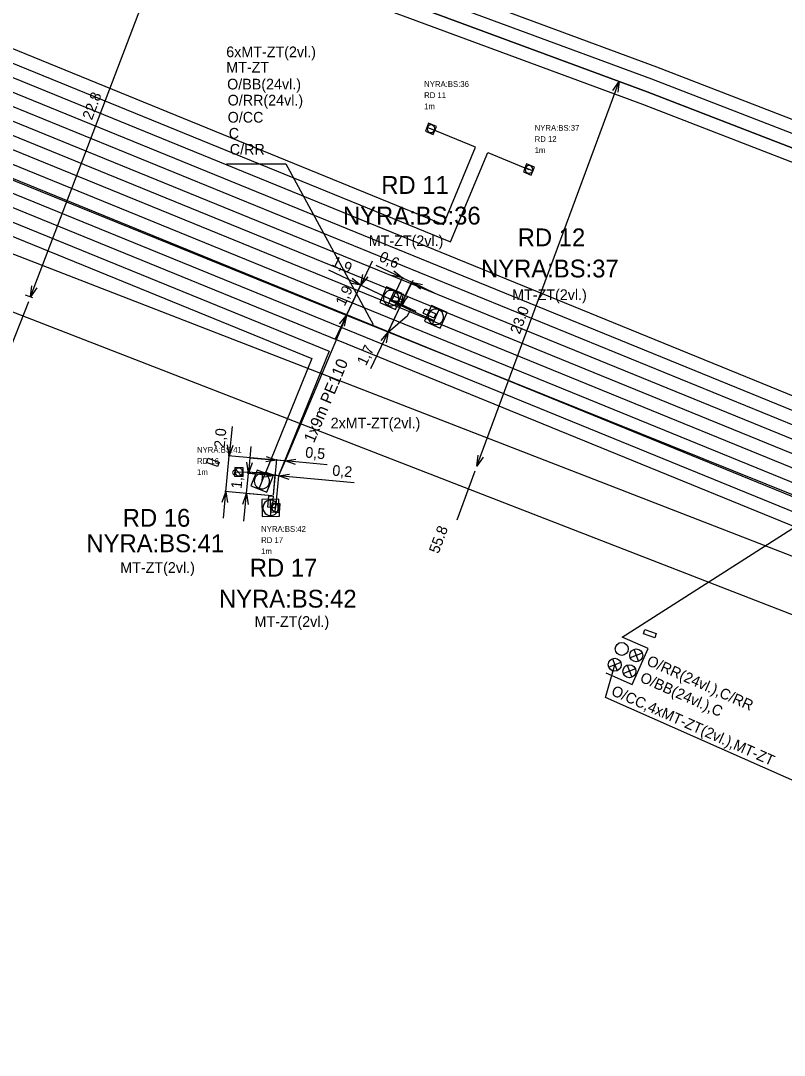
# Model space of a CAD drawing. Extents: x -836739 to -834468, y -1071001 to -1070126.
# Drawn here: x -836340.8 to -836298, y -1070459.3 to -1070401.3 of the extents above; entities that cross this region are included whole.
import ezdxf

# ---------------------------------------------------------------- set-up
doc = ezdxf.new("R2010")
doc.units = 0
for name, color, linetype in [('f001_pol_linie', 7, 'Continuous'), ('f002_inz_linie_mimo_CETIN', 7, 'Continuous'), ('f003_opt_sit_texty', 7, 'Continuous'), ('f003_opt_sit_znacky', 7, 'Continuous'), ('f003_vynaseci_cary', 7, 'Continuous'), ('f006_osa_trasy', 7, 'Continuous'), ('f006_stp_koty', 7, 'Continuous'), ('f006_stp_linie', 7, 'Continuous'), ('f006_stp_texty', 7, 'Continuous'), ('f007_rezkynet_linie', 7, 'Continuous'), ('f007_rezkynet_texty', 7, 'Continuous'), ('f007_rezkynet_znacky', 7, 'Continuous'), ('f309_rozvadec_opt', 7, 'Continuous'), ('f309_rozvadec_opt_ann', 7, 'Continuous'), ('f309_trubicka', 7, 'Continuous'), ('f309_trubka', 7, 'Continuous')]:
    doc.layers.add(name, color=color, linetype=linetype)

msp = doc.modelspace()

# ---------------------------------------------------------------- linework, layer by layer
at = {"layer": 'f001_pol_linie'}
for points in [[(-836015.21, -1070459.49), (-836021.84, -1070470.53), (-836029.29, -1070480.55), (-836039.31, -1070497.89), (-836043.1, -1070509.87), (-836044.22, -1070522.08), (-836111.13, -1070487.77), (-836123.74, -1070483.53), (-836128.61, -1070481.99), (-836211.76, -1070460.38), (-836245.95, -1070449.75), (-836279.43, -1070438.33), (-836363.94, -1070405.58)], [(-836046.6, -1070544.35), (-836045.64, -1070538.23), (-836044.38, -1070528.39), (-836045.14, -1070525.37), (-836047.92, -1070523.71), (-836112.97, -1070490.6), (-836124.66, -1070486.54), (-836132.47, -1070484.33), (-836212.77, -1070463.28), (-836247.95, -1070452.55), (-836280.73, -1070441.12), (-836361.89, -1070409.63)]]:
    msp.add_lwpolyline(points, dxfattribs=at)
at = {"layer": 'f002_inz_linie_mimo_CETIN'}
for points in [[(-836319.98, -1070416.95), (-836319.87, -1070416.72), (-836319.28, -1070417), (-836319.39, -1070417.23)], [(-836319.98, -1070416.95), (-836319.87, -1070416.72), (-836319.28, -1070417), (-836319.39, -1070417.23)], [(-836319.98, -1070416.95), (-836319.39, -1070417.23)], [(-836319.98, -1070416.95), (-836319.39, -1070417.23)], [(-836318.22, -1070417.68), (-836318.12, -1070417.45), (-836317.52, -1070417.72), (-836317.62, -1070417.95)], [(-836318.22, -1070417.68), (-836318.12, -1070417.45), (-836317.52, -1070417.72), (-836317.62, -1070417.95)], [(-836318.22, -1070417.68), (-836317.62, -1070417.95)], [(-836318.22, -1070417.68), (-836317.62, -1070417.95)], [(-836329.68, -1070426.06), (-836329.77, -1070426.29), (-836330.38, -1070426.06), (-836330.29, -1070425.83)], [(-836329.68, -1070426.06), (-836329.77, -1070426.29), (-836330.38, -1070426.06), (-836330.29, -1070425.83)], [(-836330.29, -1070425.83), (-836329.68, -1070426.06)], [(-836330.29, -1070425.83), (-836329.68, -1070426.06)], [(-836326.7, -1070428.6), (-836326.95, -1070428.58), (-836326.89, -1070427.93), (-836326.64, -1070427.95)], [(-836326.7, -1070428.6), (-836326.95, -1070428.58), (-836326.89, -1070427.93), (-836326.64, -1070427.95)], [(-836326.64, -1070427.95), (-836326.7, -1070428.6)], [(-836326.64, -1070427.95), (-836326.7, -1070428.6)], [(-836305.14, -1070435.66), (-836305.22, -1070435.9), (-836305.86, -1070435.68), (-836305.78, -1070435.44)], [(-836305.14, -1070435.66), (-836305.22, -1070435.9), (-836305.86, -1070435.68), (-836305.78, -1070435.44)], [(-836305.78, -1070435.44), (-836305.14, -1070435.66)], [(-836305.78, -1070435.44), (-836305.14, -1070435.66)]]:
    msp.add_lwpolyline(points, dxfattribs=at)
at = {"layer": 'f003_opt_sit_znacky'}
for p, q in [((-836319.859, -1070416.443), (-836320.201, -1070417.237)), ((-836319.859, -1070416.444), (-836319.859, -1070416.443)), ((-836317.345, -1070417.495), (-836317.695, -1070418.285)), ((-836317.345, -1070417.496), (-836317.345, -1070417.495)), ((-836327.121, -1070426.708), (-836327.439, -1070427.512)), ((-836327.122, -1070426.709), (-836327.121, -1070426.708)), ((-836326.777, -1070429.042), (-836326.803, -1070428.178)), ((-836326.777, -1070429.041), (-836326.777, -1070429.042))]:
    msp.add_line(p, q, dxfattribs=at)
for points in [[(-836320.658, -1070417.092), (-836319.777, -1070417.472), (-836319.397, -1070416.59), (-836320.279, -1070416.21)], [(-836318.151, -1070418.135), (-836317.274, -1070418.525), (-836316.884, -1070417.647), (-836317.761, -1070417.257)], [(-836327.9, -1070427.381), (-836327.007, -1070427.734), (-836326.655, -1070426.841), (-836327.548, -1070426.488)], [(-836326.327, -1070428.116), (-836327.287, -1070428.145), (-836327.258, -1070429.104), (-836326.298, -1070429.075)]]:
    msp.add_lwpolyline(points, close=True, dxfattribs=at)
for centre, start, end in [((-836320.027, -1070416.841), 67.04609, 246.31849), ((-836320.027, -1070416.842), 246.27775, 67.08598), ((-836317.517, -1070417.891), 66.40131, 245.67371), ((-836317.517, -1070417.892), 245.63296, 66.4412), ((-836327.277, -1070427.111), 68.82282, 248.09523), ((-836327.277, -1070427.112), 248.05448, 68.86271), ((-836326.793, -1070428.61), 91.33116, 272.13939), ((-836326.793, -1070428.61), 272.0995, 91.37191)]:
    msp.add_arc(centre, 0.432, start, end, dxfattribs=at)
at = {"layer": 'f003_vynaseci_cary'}
msp.add_lwpolyline([(-836329.27, -1070409.3), (-836325.94, -1070409.3), (-836321.04, -1070418.33)], dxfattribs=at)
at = {"layer": 'f006_osa_trasy'}
for points in [[(-836259.51, -1070422.49), (-836273.33, -1070418.13), (-836279.63, -1070415.33), (-836305.65, -1070405.26), (-836332.15, -1070395.46), (-836355.51, -1070386.15), (-836363.32, -1070381.37), (-836370.68, -1070374.62), (-836386.63, -1070361.4), (-836412.6, -1070344.19), (-836444.52, -1070318.16), (-836450.35, -1070293.64), (-836451.12, -1070284.95), (-836453.47, -1070277.02), (-836456.68, -1070270.62)], [(-836322.53, -1070417.81), (-836341.09, -1070410.29), (-836350.1, -1070406.54)], [(-836318.94, -1070417.52), (-836320.09, -1070416.97), (-836320.03, -1070416.84)], [(-836322.53, -1070417.81), (-836325.98, -1070425.98), (-836326.34, -1070426.82)], [(-836320.19, -1070418.75), (-836322.53, -1070417.81)], [(-836320.19, -1070418.75), (-836319.1, -1070417.82), (-836318.94, -1070417.52)], [(-836318.94, -1070417.52), (-836317.61, -1070418.1), (-836317.52, -1070417.89)], [(-836288.87, -1070431.6), (-836297.25, -1070427.97), (-836320.19, -1070418.75)], [(-836326.34, -1070426.82), (-836327.25, -1070426.64), (-836327.28, -1070427.11)], [(-836326.34, -1070426.82), (-836326.51, -1070428.61), (-836326.79, -1070428.61)]]:
    msp.add_lwpolyline(points, dxfattribs=at)
at = {"layer": 'f006_stp_koty'}
for p, q in [((-836321.085, -1070414.765), (-836321.728, -1070416.12)), ((-836320.88, -1070414.993), (-836319.388, -1070415.702)), ((-836323.536, -1070415.262), (-836321.728, -1070416.12)), ((-836322.53, -1070417.81), (-836321.728, -1070416.12)), ((-836322.504, -1070417.756), (-836321.702, -1070416.066)), ((-836320.034, -1070416.924), (-836321.782, -1070416.095)), ((-836319.98, -1070416.95), (-836321.728, -1070416.12)), ((-836320.164, -1070418.696), (-836318.836, -1070415.897)), ((-836319.954, -1070416.896), (-836319.362, -1070415.648)), ((-836318.811, -1070415.844), (-836319.454, -1070417.2)), ((-836319.388, -1070415.702), (-836318.862, -1070415.951)), ((-836317.507, -1070416.594), (-836318.862, -1070415.951)), ((-836320.19, -1070418.75), (-836319.454, -1070417.2)), ((-836318.625, -1070417.593), (-836319.98, -1070416.95)), ((-836319.926, -1070416.976), (-836319.4, -1070417.225)), ((-836323.173, -1070419.165), (-836322.53, -1070417.81)), ((-836321.162, -1070420.798), (-836320.19, -1070418.75)), ((-836328.957, -1070424.043), (-836329.109, -1070425.691)), ((-836327.9, -1070425.17), (-836328.038, -1070426.663)), ((-836329.295, -1070427.705), (-836329.109, -1070425.691)), ((-836326.04, -1070425.974), (-836329.169, -1070425.686)), ((-836327.948, -1070425.798), (-836326.454, -1070425.936)), ((-836326.634, -1070427.89), (-836326.449, -1070425.876)), ((-836325.98, -1070425.98), (-836326.454, -1070425.936)), ((-836323.623, -1070426.198), (-836325.98, -1070425.98)), ((-836326.4, -1070426.814), (-836328.098, -1070426.658)), ((-836328.144, -1070427.811), (-836328.038, -1070426.663)), ((-836328.028, -1070426.664), (-836326.534, -1070426.802)), ((-836326.634, -1070427.89), (-836326.529, -1070426.742)), ((-836326.34, -1070426.82), (-836326.534, -1070426.802)), ((-836322.107, -1070427.211), (-836326.34, -1070426.82)), ((-836329.433, -1070429.199), (-836329.295, -1070427.705)), ((-836326.7, -1070427.944), (-836329.355, -1070427.699)), ((-836328.288, -1070429.366), (-836328.144, -1070427.811)), ((-836326.7, -1070427.944), (-836328.204, -1070427.806))]:
    msp.add_line(p, q, dxfattribs=at)
for points in [[(-836340.268, -1070416.773), (-836332.149, -1070395.46)], [(-836315.213, -1070426.276), (-836307.226, -1070404.677)], [(-836307.574, -1070405.187), (-836307.226, -1070404.677), (-836307.293, -1070405.291)], [(-836321.335, -1070415.643), (-836321.728, -1070416.12), (-836321.606, -1070415.514)], [(-836319.865, -1070415.309), (-836319.388, -1070415.702), (-836319.994, -1070415.58)], [(-836339.914, -1070416.265), (-836340.268, -1070416.773), (-836340.194, -1070416.158)], [(-836322.206, -1070415.728), (-836321.728, -1070416.12), (-836322.335, -1070415.999)], [(-836318.384, -1070416.344), (-836318.862, -1070415.951), (-836318.255, -1070416.073)], [(-836340.143, -1070416.821), (-836340.548, -1070416.666)], [(-836319.061, -1070416.722), (-836319.454, -1070417.2), (-836319.332, -1070416.593)], [(-836340.379, -1070417.053), (-836341.625, -1070420.232)], [(-836319.502, -1070417.343), (-836319.98, -1070416.95), (-836319.374, -1070417.072)], [(-836322.923, -1070418.288), (-836322.53, -1070417.81), (-836322.652, -1070418.416)], [(-836320.583, -1070419.228), (-836320.19, -1070418.75), (-836320.312, -1070419.356)], [(-836328.905, -1070425.107), (-836329.109, -1070425.691), (-836329.204, -1070425.08)], [(-836327.834, -1070426.08), (-836328.038, -1070426.663), (-836328.132, -1070426.052)], [(-836327.038, -1070425.732), (-836326.454, -1070425.936), (-836327.065, -1070426.03)], [(-836325.396, -1070426.185), (-836325.98, -1070425.98), (-836325.369, -1070425.886)], [(-836314.864, -1070425.765), (-836315.213, -1070426.276), (-836315.145, -1070425.661)], [(-836327.118, -1070426.598), (-836326.534, -1070426.802), (-836327.145, -1070426.896)], [(-836315.317, -1070426.557), (-836316.329, -1070429.293)], [(-836325.756, -1070427.025), (-836326.34, -1070426.82), (-836325.729, -1070426.726)], [(-836329.5, -1070428.289), (-836329.295, -1070427.705), (-836329.201, -1070428.316)], [(-836328.349, -1070428.395), (-836328.144, -1070427.811), (-836328.05, -1070428.422)]]:
    msp.add_lwpolyline(points, dxfattribs=at)
at = {"layer": 'f006_stp_linie'}
msp.add_lwpolyline([(-836322.53, -1070417.81), (-836325.98, -1070425.98)], dxfattribs=at)
at = {"layer": 'f007_rezkynet_linie'}
for points in [[(-836307.058, -1070435.86), (-836295.973, -1070428.796)], [(-836296.531, -1070444.332), (-836307.992, -1070439.257), (-836307.472, -1070437.416)]]:
    msp.add_lwpolyline(points, dxfattribs=at)
at = {"layer": 'f007_rezkynet_znacky'}
for p, q in [((-836305.595, -1070436.508), (-836307.058, -1070435.86)), ((-836306.488, -1070438.526), (-836305.595, -1070436.508)), ((-836307.603, -1070437.077), (-836307.341, -1070437.754)), ((-836305.927, -1070436.758), (-836306.605, -1070437.019)), ((-836306.397, -1070436.55), (-836306.135, -1070437.227)), ((-836307.133, -1070437.285), (-836307.811, -1070437.546)), ((-836306.311, -1070437.649), (-836306.988, -1070437.91)), ((-836306.781, -1070437.441), (-836306.518, -1070438.118)), ((-836307.966, -1070437.872), (-836306.503, -1070438.519))]:
    msp.add_line(p, q, dxfattribs=at)
for centre in [(-836307.08, -1070436.528), (-836306.266, -1070436.889), (-836307.472, -1070437.416), (-836306.65, -1070437.78)]:
    msp.add_circle(centre, 0.363, dxfattribs=at)
at = {"layer": 'f309_rozvadec_opt'}
for p, q in [((-836317.989, -1070407.257), (-836317.59, -1070407.422)), ((-836317.989, -1070407.257), (-836317.989, -1070407.257)), ((-836312.089, -1070409.699), (-836312.488, -1070409.534)), ((-836312.089, -1070409.699), (-836312.089, -1070409.699)), ((-836328.786, -1070426.596), (-836328.354, -1070426.607)), ((-836328.785, -1070426.596), (-836328.786, -1070426.596)), ((-836326.529, -1070428.825), (-836326.488, -1070428.395)), ((-836326.529, -1070428.825), (-836326.529, -1070428.825))]:
    msp.add_line(p, q, dxfattribs=at)
for points in [[(-836317.659, -1070407.652), (-836317.475, -1070407.208), (-836317.919, -1070407.025), (-836318.103, -1070407.468)], [(-836312.419, -1070409.304), (-836312.603, -1070409.748), (-836312.159, -1070409.931), (-836311.975, -1070409.488)], [(-836328.337, -1070426.847), (-836328.324, -1070426.367), (-836328.803, -1070426.354), (-836328.816, -1070426.834)], [(-836326.248, -1070428.394), (-836326.726, -1070428.348), (-836326.771, -1070428.826), (-836326.294, -1070428.872)]]:
    msp.add_lwpolyline(points, close=True, dxfattribs=at)
for centre, start, end in [((-836317.789, -1070407.338), 157.84514, 337.11755), ((-836317.789, -1070407.338), 337.0768, 157.88504), ((-836312.289, -1070409.618), 157.07592, 337.88415), ((-836312.289, -1070409.618), 337.84426, 157.11667), ((-836328.57, -1070426.6), 178.83014, 358.10255), ((-836328.57, -1070426.6), 358.0618, 178.87003), ((-836326.51, -1070428.61), 84.17023, 264.97846), ((-836326.51, -1070428.61), 264.93857, 84.21098)]:
    msp.add_arc(centre, 0.216, start, end, dxfattribs=at)
at = {"layer": 'f309_trubicka'}
for points in [[(-836400.273, -1070369.489), (-836398.353, -1070370.882), (-836399.415, -1070374.242), (-836401.469, -1070380.743), (-836403.793, -1070387.056), (-836399.084, -1070388.826), (-836381.692, -1070398.154), (-836351.184, -1070409.34), (-836324.48, -1070420.23), (-836327.076, -1070426.64), (-836328.57, -1070426.6)], [(-836400.273, -1070369.489), (-836397.638, -1070371.108), (-836398.7, -1070374.468), (-836400.759, -1070380.986), (-836402.832, -1070386.616), (-836398.773, -1070388.142), (-836381.384, -1070397.468), (-836350.913, -1070408.64), (-836323.504, -1070419.818), (-836326.34, -1070426.82), (-836326.51, -1070428.61)], [(-836400.273, -1070369.489), (-836399.069, -1070370.656), (-836400.13, -1070374.016), (-836402.617, -1070381.89), (-836396.907, -1070384.038), (-836379.536, -1070393.352), (-836349.287, -1070404.44), (-836286.052, -1070430.233), (-836290.016, -1070440.999), (-836290.881, -1070443.349)], [(-836400.273, -1070369.489), (-836396.208, -1070371.559), (-836397.27, -1070374.92), (-836399.339, -1070381.472), (-836399.355, -1070381.515), (-836396.285, -1070382.67), (-836378.92, -1070391.98), (-836348.745, -1070403.04), (-836289.137, -1070427.354), (-836286.713, -1070421.411), (-836283.062, -1070422.901)], [(-836400.273, -1070369.489), (-836394.777, -1070372.011), (-836395.84, -1070375.372), (-836397.495, -1070380.612), (-836395.663, -1070381.302), (-836378.304, -1070390.608), (-836348.203, -1070401.64), (-836289.959, -1070425.398), (-836287.821, -1070420.156), (-836276.772, -1070391.607), (-836279.008, -1070390.66), (-836276.322, -1070384.183), (-836278.31, -1070383.359), (-836277.858, -1070382.269)], [(-836400.273, -1070369.489), (-836395.493, -1070371.785), (-836396.555, -1070375.146), (-836398.424, -1070381.064), (-836395.974, -1070381.986), (-836378.612, -1070391.294), (-836348.474, -1070402.34), (-836289.548, -1070426.376), (-836287.124, -1070420.433), (-836275.81, -1070391.2), (-836278.03, -1070390.26), (-836275.63, -1070384.47), (-836273.812, -1070385.224), (-836273.367, -1070384.131)], [(-836400.273, -1070369.489), (-836394.062, -1070372.237), (-836395.125, -1070375.598), (-836396.566, -1070380.161), (-836395.352, -1070380.618), (-836377.996, -1070389.922), (-836347.932, -1070400.94), (-836316.686, -1070413.686), (-836314.602, -1070408.659), (-836312.289, -1070409.618)], [(-836400.273, -1070369.489), (-836393.347, -1070372.463), (-836394.41, -1070375.824), (-836395.637, -1070379.709), (-836395.041, -1070379.934), (-836377.688, -1070389.236), (-836347.661, -1070400.24), (-836317.093, -1070412.71), (-836315.295, -1070408.372), (-836317.789, -1070407.338)], [(-836397.141, -1070372.024), (-836397.985, -1070374.694), (-836400.049, -1070381.229), (-836400.305, -1070381.924), (-836400.312, -1070381.956), (-836396.596, -1070383.354), (-836379.228, -1070392.666), (-836349.016, -1070403.74), (-836288.726, -1070428.332), (-836286.302, -1070422.389), (-836283.345, -1070423.595)]]:
    msp.add_lwpolyline(points, dxfattribs=at)
at = {"layer": 'f309_trubka'}
for points in [[(-836261.299, -1070421.137), (-836273.064, -1070417.427), (-836279.342, -1070414.637), (-836305.385, -1070404.559), (-836331.881, -1070394.76), (-836354.106, -1070385.902), (-836354.759, -1070385.663), (-836362.708, -1070381.226), (-836386.046, -1070360.976), (-836412.515, -1070343.515), (-836444.58, -1070317.908), (-836450.178, -1070294.362), (-836450.35, -1070293.64), (-836451.12, -1070284.95), (-836453.47, -1070277.02), (-836455.659, -1070272.655)], [(-836454.989, -1070272.319), (-836452.77, -1070276.743), (-836450.38, -1070284.809), (-836449.608, -1070293.52), (-836449.436, -1070294.242), (-836443.91, -1070317.483), (-836412.074, -1070342.908), (-836385.592, -1070360.377), (-836362.275, -1070380.609), (-836354.445, -1070384.979), (-836353.838, -1070385.201), (-836331.612, -1070394.06), (-836305.12, -1070403.858), (-836279.054, -1070413.944), (-836272.798, -1070416.724), (-836261.073, -1070420.421)], [(-836457, -1070273.327), (-836454.87, -1070277.574), (-836452.6, -1070285.232), (-836451.834, -1070293.88), (-836451.663, -1070294.602), (-836445.92, -1070318.758), (-836413.397, -1070344.729), (-836386.954, -1070362.174), (-836363.574, -1070382.46), (-836355.387, -1070387.031), (-836354.642, -1070387.304), (-836332.419, -1070396.16), (-836305.915, -1070405.961), (-836279.918, -1070416.023), (-836273.596, -1070418.833), (-836262.401, -1070422.363)], [(-836456.329, -1070272.991), (-836454.17, -1070277.297), (-836451.86, -1070285.091), (-836451.092, -1070293.76), (-836445.25, -1070318.333), (-836412.956, -1070344.122), (-836386.5, -1070361.575), (-836363.141, -1070381.843), (-836355.073, -1070386.347), (-836354.374, -1070386.603), (-836332.15, -1070395.46), (-836305.65, -1070405.26), (-836279.63, -1070415.33), (-836273.33, -1070418.13), (-836262.175, -1070421.648)], [(-836257.543, -1070422.322), (-836258.258, -1070422.096), (-836259.283, -1070421.772), (-836260.99, -1070422.47), (-836266.6, -1070439.21), (-836271.52, -1070438.59), (-836350.1, -1070406.54), (-836380.46, -1070395.41), (-836397.84, -1070386.09), (-836408, -1070382.27), (-836428.93, -1070370.15), (-836446.35, -1070358.45), (-836497.8, -1070313.84), (-836500.259, -1070310.812)], [(-836499.139, -1070311.001), (-836497.259, -1070313.316), (-836445.894, -1070357.853), (-836428.533, -1070369.513), (-836407.678, -1070381.59), (-836397.529, -1070385.406), (-836380.152, -1070394.724), (-836349.829, -1070405.84), (-836271.328, -1070437.858), (-836267.116, -1070438.389), (-836261.592, -1070421.906), (-836259.316, -1070420.975), (-836258.032, -1070421.38), (-836257.317, -1070421.606)], [(-836501.069, -1070312.194), (-836498.882, -1070314.888), (-836447.262, -1070359.644), (-836429.724, -1070371.424), (-836408.644, -1070383.63), (-836398.462, -1070387.458), (-836381.076, -1070396.782), (-836350.642, -1070407.94), (-836271.904, -1070440.054), (-836265.568, -1070440.852), (-836259.786, -1070423.598), (-836259.218, -1070423.366), (-836257.995, -1070423.753)], [(-836499.902, -1070312.441), (-836498.341, -1070314.364), (-836446.806, -1070359.047), (-836429.327, -1070370.787), (-836408.322, -1070382.95), (-836398.151, -1070386.774), (-836380.768, -1070396.096), (-836350.371, -1070407.24), (-836271.712, -1070439.322), (-836266.084, -1070440.031), (-836260.388, -1070423.034), (-836259.25, -1070422.569), (-836257.769, -1070423.038)], [(-836400.845, -1070373.79), (-836403.452, -1070382.042), (-836403.525, -1070382.35), (-836397.218, -1070384.722), (-836379.844, -1070394.038), (-836349.558, -1070405.14), (-836287.006, -1070430.654), (-836290.72, -1070440.74)]]:
    msp.add_lwpolyline(points, dxfattribs=at)

# ---------------------------------------------------------------- texts
at = {"layer": 'f003_opt_sit_texty'}
for s, height, p in [('6xMT-ZT(2vl.)', 0.6, (-836329.28, -1070403.32)), ('MT-ZT', 0.6, (-836329.28, -1070404.18)), ('O/BB(24vl.)', 0.6, (-836329.23, -1070405.13)), ('O/RR(24vl.)', 0.6, (-836329.2, -1070406.03)), ('O/CC', 0.6, (-836329.2, -1070406.99)), ('C', 0.6, (-836329.14, -1070407.89)), ('C/RR', 0.6, (-836329.08, -1070408.79)), ('RD 11', 1, (-836320.58, -1070410.99)), ('NYRA:BS:36', 1, (-836322.73, -1070412.71)), ('MT-ZT(2vl.)', 0.6, (-836321.28, -1070413.92)), ('RD 12', 1, (-836312.92, -1070413.93)), ('NYRA:BS:37', 1, (-836314.98, -1070415.68)), ('MT-ZT(2vl.)', 0.6, (-836313.23, -1070416.95)), ('2xMT-ZT(2vl.)', 0.6, (-836323.42, -1070424.15)), ('RD 16', 1, (-836335.09, -1070429.67)), ('NYRA:BS:41', 1, (-836337.13, -1070431.1)), ('MT-ZT(2vl.)', 0.6, (-836335.23, -1070432.26)), ('RD 17', 1, (-836327.96, -1070432.47)), ('NYRA:BS:42', 1, (-836329.69, -1070434.21)), ('MT-ZT(2vl.)', 0.6, (-836327.69, -1070435.29))]:
    msp.add_text(s, height=height, dxfattribs=at).set_placement(p)
at = {"layer": 'f006_stp_koty'}
for s, rotation, p in [('22.8', 69.15, (-836336.821, -1070406.881)), ('0,6', 334.61209, (-836320.752, -1070414.722)), ('1,9', 334.61209, (-836323.408, -1070414.991)), ('1,9', 64.61209, (-836322.636, -1070417.333)), ('23.0', 69.71, (-836312.806, -1070418.902)), ('1,7', 64.61209, (-836321.433, -1070420.669)), ('2,0', 84.7261, (-836329.373, -1070425.285)), ('0,5', 354.7261, (-836324.866, -1070425.782)), ('1,2', 84.7261, (-836328.422, -1070427.558)), ('0,2', 354.7261, (-836323.349, -1070426.795)), ('55.8', 69.7, (-836317.362, -1070431.219))]:
    msp.add_text(s, height=0.6, rotation=rotation, dxfattribs=at).set_placement(p)
at = {"layer": 'f006_stp_texty'}
msp.add_text('1x9m PE110', height=0.65, rotation=67.1068, dxfattribs=at).set_placement((-836324.358, -1070425.008))
at = {"layer": 'f007_rezkynet_texty'}
for s, p in [('O/RR(24vl.),C/RR', (-836305.731, -1070437.412)), ('O/BB(24vl.),C', (-836306.104, -1070438.348)), ('O/CC,4xMT-ZT(2vl.),MT-ZT', (-836307.719, -1070439.098))]:
    msp.add_text(s, height=0.6, rotation=336.11529, dxfattribs=at).set_placement(p)
at = {"layer": 'f309_rozvadec_opt_ann'}
for s, p in [('NYRA:BS:36', (-836318.17, -1070404.988)), ('RD 11', (-836318.17, -1070405.613)), ('1m', (-836318.17, -1070406.238)), ('NYRA:BS:37', (-836311.97, -1070407.448)), ('RD 12', (-836311.97, -1070408.073)), ('1m', (-836311.97, -1070408.698)), ('NYRA:BS:41', (-836330.92, -1070425.518)), ('RD 16', (-836330.92, -1070426.143)), ('1m', (-836330.92, -1070426.768)), ('NYRA:BS:42', (-836327.32, -1070429.958)), ('RD 17', (-836327.32, -1070430.583)), ('1m', (-836327.32, -1070431.208))]:
    msp.add_text(s, height=0.325, dxfattribs=at).set_placement(p)

doc.saveas('drawing.dxf')
